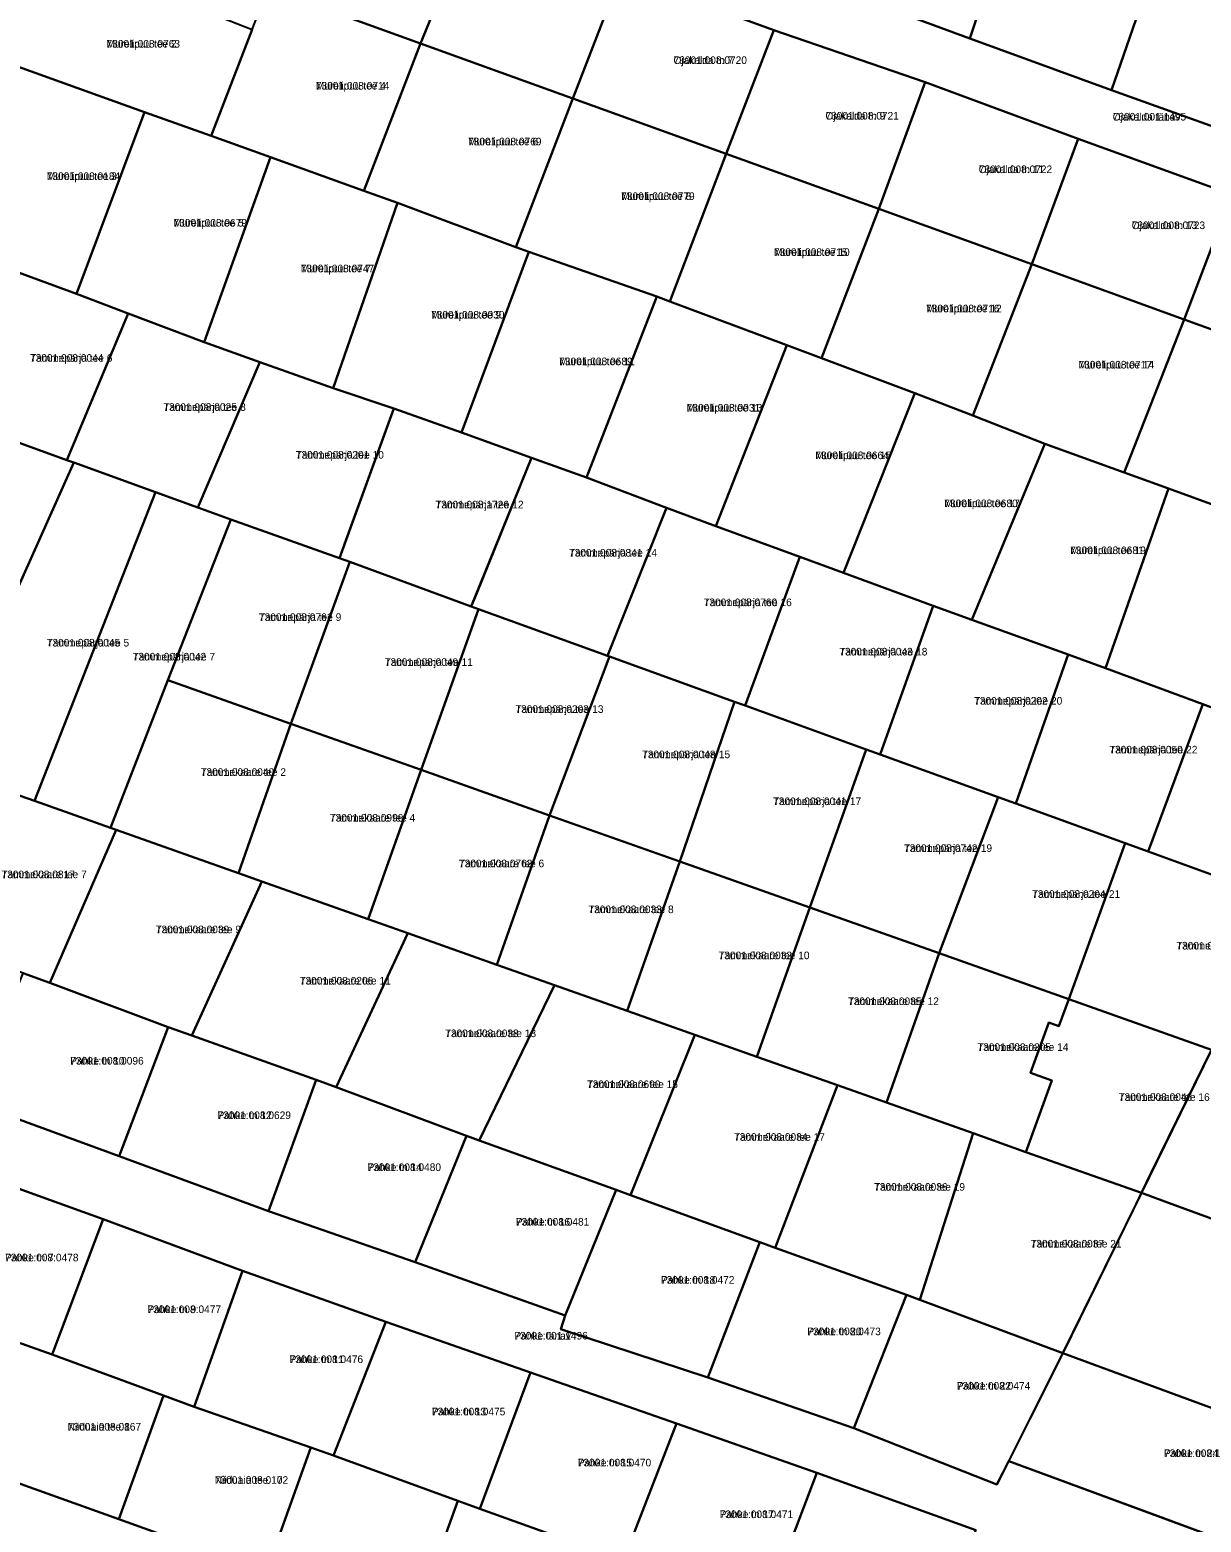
# Model space of a CAD drawing. Extents: x 524000 to 564260, y 6469338 to 6496391.
# Drawn here: x 535399.1 to 535630.3, y 6471359.9 to 6471654.6 of the extents above; entities that cross this region are included whole.
import ezdxf

# ---------------------------------------------------------------- set-up
doc = ezdxf.new("R2010")
doc.units = 0
for name, color, linetype in [('L_AADRESS', 7, 'Continuous'), ('PIIR', 7, 'Continuous'), ('TUNNUS', 7, 'Continuous')]:
    doc.layers.add(name, color=color, linetype=linetype)

msp = doc.modelspace()

# ---------------------------------------------------------------- linework, layer by layer
at = {"layer": 'PIIR'}
for points in [[(535636.37, 6471622.1), (535605.99, 6471633.1), (535575.78, 6471644.26), (535545.95, 6471654.54), (535515.72, 6471665.59), (535486.15, 6471676.39), (535455.47, 6471687.48), (535447.79, 6471690.25), (535461.42, 6471697.61), (535501.62, 6471683.31), (535528.82, 6471673.51), (535557.22, 6471663.01), (535584.62, 6471652.91), (535612.62, 6471642.71), (535639.99, 6471632.87)], [(535387.55, 6471442.79), (535416.68, 6471432.16), (535446.16, 6471421.31), (535475.12, 6471411.21), (535504.76, 6471400.7), (535503.9, 6471397.99), (535532.92, 6471388.42), (535561.75, 6471378.45), (535589.97, 6471367.28), (535592.34, 6471371.9), (535645.63, 6471352.25)], [(535585.83, 6471358.28), (535554.41, 6471369.63), (535526.7, 6471379.34), (535497.92, 6471389.42), (535469.32, 6471399.44), (535441.03, 6471409.53), (535413.56, 6471419.69), (535385.56, 6471429.81)], [(535321.36, 6471351.63), (535304.08, 6471400.35), (535329.03, 6471391.87), (535358.51, 6471381.29), (535387.56, 6471370.87), (535416.63, 6471360.43), (535445.69, 6471350)]]:
    msp.add_lwpolyline(points, dxfattribs=at)
for points in [[(535565.62, 6471688.81), (535584.52, 6471682.31), (535593.32, 6471679.01), (535584.62, 6471652.91), (535557.22, 6471663.01)], [(535455.47, 6471687.48), (535486.15, 6471676.39), (535476.16, 6471651.91), (535446.08, 6471662.8)], [(535593.32, 6471679.01), (535614.72, 6471671.41), (535621.6, 6471668.85), (535612.62, 6471642.71), (535584.62, 6471652.91)], [(535486.15, 6471676.39), (535515.72, 6471665.59), (535506.24, 6471641.03), (535476.16, 6471651.91)], [(535380.64, 6471653.45), (535385.87, 6471656.69), (535407.58, 6471668.53), (535442.96, 6471654.66), (535434.86, 6471633.66), (535421.72, 6471638.36), (535395.91, 6471647.63)], [(535621.6, 6471668.85), (535643.31, 6471660.9), (535649.15, 6471658.62), (535639.99, 6471632.87), (535612.62, 6471642.71)], [(535515.72, 6471665.59), (535545.95, 6471654.54), (535536.51, 6471630.12), (535506.24, 6471641.03)], [(535434.86, 6471633.66), (535442.96, 6471654.66), (535446.08, 6471662.8), (535476.16, 6471651.91), (535464.96, 6471622.82), (535446.58, 6471629.46)], [(535545.95, 6471654.54), (535575.78, 6471644.26), (535566.68, 6471619.22), (535536.51, 6471630.12)], [(535464.96, 6471622.82), (535476.16, 6471651.91), (535506.24, 6471641.03), (535495, 6471611.68), (535471.61, 6471620.42)], [(535383.06, 6471611.74), (535395.91, 6471647.63), (535421.72, 6471638.36), (535408.26, 6471602.44), (535392.25, 6471608.35)], [(535575.78, 6471644.26), (535605.99, 6471633.1), (535596.84, 6471608.35), (535566.68, 6471619.22)], [(535495, 6471611.68), (535506.24, 6471641.03), (535536.51, 6471630.12), (535525.38, 6471600.97), (535522.85, 6471601.91), (535497.53, 6471610.74)], [(535408.26, 6471602.44), (535421.72, 6471638.36), (535434.86, 6471633.66), (535446.58, 6471629.46), (535433.46, 6471592.9), (535418.44, 6471598.59)], [(535605.99, 6471633.1), (535636.37, 6471622.1), (535626.91, 6471597.4), (535596.84, 6471608.35)], [(535536.51, 6471630.12), (535566.68, 6471619.22), (535555.32, 6471589.78), (535548.47, 6471592.34), (535525.38, 6471600.97)], [(535433.46, 6471592.9), (535446.58, 6471629.46), (535464.96, 6471622.82), (535471.61, 6471620.42), (535458.96, 6471583.86), (535444.48, 6471588.99)], [(535636.37, 6471622.1), (535666.31, 6471611.28), (535656.91, 6471586.54), (535626.91, 6471597.4)], [(535458.96, 6471583.86), (535471.61, 6471620.42), (535495, 6471611.68), (535497.53, 6471610.74), (535484.26, 6471575.09), (535470.88, 6471579.82)], [(535555.32, 6471589.78), (535566.68, 6471619.22), (535596.84, 6471608.35), (535585.23, 6471578.4), (535573.79, 6471582.87)], [(535484.26, 6471575.09), (535497.53, 6471610.74), (535522.85, 6471601.91), (535508.97, 6471566.19), (535498.08, 6471570.05)], [(535392.25, 6471608.35), (535408.26, 6471602.44), (535418.44, 6471598.59), (535406.34, 6471569.64), (535379.72, 6471579.28)], [(535585.23, 6471578.4), (535596.84, 6471608.35), (535626.91, 6471597.4), (535615.11, 6471567.16), (535599.44, 6471572.85)], [(535508.97, 6471566.19), (535522.85, 6471601.91), (535525.38, 6471600.97), (535548.47, 6471592.34), (535534.46, 6471556.56), (535524.77, 6471560.22)], [(535407.73, 6471569.15), (535406.34, 6471569.64), (535418.44, 6471598.59), (535433.46, 6471592.9), (535444.48, 6471588.99), (535432.23, 6471560.27), (535423.84, 6471563.31)], [(535615.11, 6471567.16), (535626.91, 6471597.4), (535656.91, 6471586.54), (535646.98, 6471562.26), (535644.74, 6471556.41), (535623.82, 6471564)], [(535534.46, 6471556.56), (535548.47, 6471592.34), (535555.32, 6471589.78), (535573.79, 6471582.87), (535559.71, 6471547.36), (535551.07, 6471550.51)], [(535432.23, 6471560.27), (535444.48, 6471588.99), (535458.96, 6471583.86), (535470.88, 6471579.82), (535460.19, 6471550.27), (535438.72, 6471557.92)], [(535368.36, 6471583.4), (535379.72, 6471579.28), (535406.34, 6471569.64), (535407.73, 6471569.15), (535395.99, 6471542.77), (535358.36, 6471557.3)], [(535559.71, 6471547.36), (535573.79, 6471582.87), (535585.23, 6471578.4), (535599.44, 6471572.85), (535585.04, 6471538.05), (535577.41, 6471540.85)], [(535498.08, 6471570.05), (535487.2, 6471543.2), (535486.18, 6471540.68), (535462.24, 6471549.51), (535460.19, 6471550.27), (535461.17, 6471553), (535470.88, 6471579.82), (535484.26, 6471575.09)], [(535599.44, 6471572.85), (535615.11, 6471567.16), (535623.82, 6471564), (535611.41, 6471528.56), (535604.03, 6471531.22), (535585.04, 6471538.05)], [(535380.94, 6471508.97), (535387.06, 6471522.71), (535395.99, 6471542.77), (535407.73, 6471569.15), (535423.84, 6471563.31), (535399.98, 6471502.3), (535384.47, 6471507.73)], [(535486.18, 6471540.68), (535498.08, 6471570.05), (535508.97, 6471566.19), (535524.77, 6471560.22), (535513.09, 6471530.98), (535487.63, 6471540.2)], [(535399.98, 6471502.3), (535423.84, 6471563.31), (535432.23, 6471560.27), (535438.72, 6471557.92), (535426.29, 6471526.15), (535414.97, 6471496.99)], [(535623.82, 6471564), (535644.74, 6471556.41), (535649.36, 6471554.73), (535636.76, 6471519.12), (535630.62, 6471521.41), (535611.41, 6471528.56)], [(535513.09, 6471530.98), (535524.77, 6471560.22), (535534.46, 6471556.56), (535551.07, 6471550.51), (535540.3, 6471521.13), (535538.17, 6471521.9), (535513.5, 6471530.83)], [(535438.72, 6471557.92), (535460.19, 6471550.27), (535462.24, 6471549.51), (535450.6, 6471517.54), (535426.29, 6471526.15)], [(535551.07, 6471550.51), (535559.71, 6471547.36), (535577.41, 6471540.85), (535566.93, 6471511.48), (535564.18, 6471512.47), (535540.3, 6471521.13)], [(535462.24, 6471549.51), (535486.18, 6471540.68), (535487.63, 6471540.2), (535476.33, 6471508.43), (535450.6, 6471517.54)], [(535487.63, 6471540.2), (535513.09, 6471530.98), (535513.5, 6471530.83), (535501.65, 6471499.46), (535476.33, 6471508.43)], [(535577.41, 6471540.85), (535585.04, 6471538.05), (535604.03, 6471531.22), (535593.71, 6471501.78), (535590.2, 6471503.05), (535566.93, 6471511.48)], [(535513.5, 6471530.83), (535538.17, 6471521.9), (535527.38, 6471490.35), (535501.65, 6471499.46)], [(535604.03, 6471531.22), (535611.41, 6471528.56), (535630.62, 6471521.41), (535619.8, 6471492.33), (535615.27, 6471493.97), (535593.71, 6471501.78)], [(535414.97, 6471496.99), (535426.29, 6471526.15), (535450.6, 6471517.54), (535440.25, 6471488.02), (535416.12, 6471496.57)], [(535538.17, 6471521.9), (535540.3, 6471521.13), (535564.18, 6471512.47), (535553.04, 6471481.26), (535527.38, 6471490.35)], [(535630.62, 6471521.41), (535636.76, 6471519.12), (535660.07, 6471510.38), (535646.63, 6471482.61), (535619.8, 6471492.33)], [(535440.25, 6471488.02), (535450.6, 6471517.54), (535476.33, 6471508.43), (535465.87, 6471478.95), (535444.86, 6471486.39)], [(535564.18, 6471512.47), (535566.93, 6471511.48), (535590.2, 6471503.05), (535588.69, 6471499.05), (535578.54, 6471472.23), (535553.04, 6471481.26)], [(535382.37, 6471503.17), (535384.47, 6471507.73), (535399.98, 6471502.3), (535414.97, 6471496.99), (535416.12, 6471496.57), (535402.97, 6471466.37), (535397.72, 6471468.32), (535370.86, 6471478.25)], [(535465.87, 6471478.95), (535476.33, 6471508.43), (535501.65, 6471499.46), (535491.25, 6471469.96), (535473.66, 6471476.19)], [(535588.69, 6471499.05), (535590.2, 6471503.05), (535593.71, 6471501.78), (535615.27, 6471493.97), (535604.15, 6471463.16), (535578.54, 6471472.23)], [(535491.25, 6471469.96), (535501.65, 6471499.46), (535527.38, 6471490.35), (535517, 6471460.84), (535502.6, 6471465.94)], [(535416.12, 6471496.57), (535440.25, 6471488.02), (535444.86, 6471486.39), (535431.05, 6471455.95), (535426.34, 6471457.64), (535402.97, 6471466.37)], [(535615.27, 6471493.97), (535619.8, 6471492.33), (535646.63, 6471482.61), (535632.36, 6471453.17), (535604.15, 6471463.16)], [(535517, 6471460.84), (535527.38, 6471490.35), (535553.04, 6471481.26), (535542.6, 6471451.77), (535530.3, 6471456.13)], [(535444.86, 6471486.39), (535465.87, 6471478.95), (535473.66, 6471476.19), (535459.51, 6471445.76), (535455.57, 6471447.23), (535431.05, 6471455.95)], [(535542.6, 6471451.77), (535553.04, 6471481.26), (535578.54, 6471472.23), (535568.14, 6471442.73), (535558.48, 6471446.15)], [(535473.66, 6471476.19), (535491.25, 6471469.96), (535502.6, 6471465.94), (535487.79, 6471435.26), (535485.25, 6471436.18), (535459.51, 6471445.76)], [(535568.14, 6471442.73), (535578.54, 6471472.23), (535604.15, 6471463.16), (535602.22, 6471457.85), (535600.22, 6471458.58), (535596.6, 6471448.62), (535600.83, 6471447.08), (535595.69, 6471432.95), (535585.27, 6471436.66)], [(535397.72, 6471468.32), (535402.97, 6471466.37), (535426.34, 6471457.64), (535416.68, 6471432.16), (535387.55, 6471442.79)], [(535502.6, 6471465.94), (535517, 6471460.84), (535530.3, 6471456.13), (535517.66, 6471424.45), (535514.8, 6471425.49), (535487.79, 6471435.26)], [(535600.83, 6471447.08), (535596.6, 6471448.62), (535600.22, 6471458.58), (535602.22, 6471457.85), (535604.15, 6471463.16), (535632.36, 6471453.17), (535618.51, 6471424.89), (535595.69, 6471432.95)], [(535426.34, 6471457.64), (535431.05, 6471455.95), (535455.57, 6471447.23), (535446.16, 6471421.31), (535416.68, 6471432.16)], [(535530.3, 6471456.13), (535542.6, 6471451.77), (535558.48, 6471446.15), (535546.17, 6471414.06), (535543.15, 6471415.14), (535517.66, 6471424.45)], [(535632.36, 6471453.17), (535661.37, 6471442.52), (535679.4, 6471435.91), (535674.06, 6471424.59), (535667.34, 6471406.98), (535654.88, 6471411.55), (535623.09, 6471423.21), (535618.51, 6471424.88), (535620.45, 6471428.85)], [(535455.57, 6471447.23), (535459.51, 6471445.76), (535485.25, 6471436.18), (535475.12, 6471411.21), (535446.16, 6471421.31)], [(535558.48, 6471446.15), (535568.14, 6471442.73), (535585.27, 6471436.66), (535574.73, 6471403.8), (535572.09, 6471404.79), (535546.17, 6471414.06)], [(535485.25, 6471436.18), (535487.79, 6471435.26), (535514.8, 6471425.49), (535504.76, 6471400.7), (535475.12, 6471411.21)], [(535585.27, 6471436.66), (535595.69, 6471432.95), (535618.51, 6471424.89), (535602.98, 6471393.22), (535574.73, 6471403.8)], [(535385.56, 6471429.81), (535413.56, 6471419.69), (535403.45, 6471392.96), (535396.41, 6471395.49), (535374.56, 6471403.35)], [(535504.76, 6471400.7), (535514.8, 6471425.49), (535517.66, 6471424.45), (535543.15, 6471415.14), (535532.92, 6471388.42), (535503.9, 6471397.99)], [(535618.51, 6471424.88), (535623.09, 6471423.21), (535654.88, 6471411.55), (535667.34, 6471406.98), (535661.59, 6471392.43), (535653.82, 6471374.57), (535628.68, 6471383.78), (535602.98, 6471393.21), (535617.44, 6471422.7)], [(535413.56, 6471419.69), (535441.03, 6471409.53), (535431.48, 6471382.63), (535425.41, 6471384.87), (535403.45, 6471392.96)], [(535543.15, 6471415.14), (535546.17, 6471414.06), (535572.09, 6471404.79), (535561.75, 6471378.45), (535532.92, 6471388.42)], [(535441.03, 6471409.53), (535469.32, 6471399.44), (535458.97, 6471373.04), (535454.52, 6471374.59), (535431.48, 6471382.63)], [(535572.09, 6471404.79), (535574.73, 6471403.8), (535602.98, 6471393.22), (535589.97, 6471367.28), (535561.75, 6471378.45)], [(535469.32, 6471399.44), (535497.92, 6471389.42), (535487.91, 6471362.47), (535483.55, 6471364.06), (535458.97, 6471373.04)], [(535396.41, 6471395.49), (535403.45, 6471392.96), (535425.41, 6471384.87), (535416.63, 6471360.43), (535387.56, 6471370.87)], [(535602.98, 6471393.21), (535628.68, 6471383.78), (535653.82, 6471374.57), (535645.63, 6471352.25), (535623.05, 6471360.57), (535592.34, 6471371.9)], [(535497.92, 6471389.42), (535526.7, 6471379.34), (535516.22, 6471352.33), (535512.6, 6471353.63), (535487.91, 6471362.47)], [(535425.41, 6471384.87), (535431.48, 6471382.63), (535454.52, 6471374.59), (535445.69, 6471350), (535416.63, 6471360.43)], [(535526.7, 6471379.34), (535554.41, 6471369.63), (535543.97, 6471342), (535541.56, 6471342.9), (535516.22, 6471352.33)], [(535454.52, 6471374.59), (535458.97, 6471373.04), (535483.55, 6471364.06), (535474.75, 6471339.57), (535445.69, 6471350)], [(535554.41, 6471369.63), (535585.83, 6471358.28), (535572.02, 6471331.99), (535543.97, 6471342)], [(535483.55, 6471364.06), (535487.91, 6471362.47), (535512.6, 6471353.63), (535503.81, 6471329.14), (535474.75, 6471339.57)]]:
    msp.add_lwpolyline(points, close=True, dxfattribs=at)

# ---------------------------------------------------------------- texts
at = {"layer": 'L_AADRESS'}
for s, p in [('Murelipuu tee 2', (535414.2, 6471651.1)), ('Ojakalda tn 7', (535526.12, 6471647.86)), ('Murelipuu tee 4', (535455.52, 6471642.81)), ('Ojakalda tn 9', (535556.11, 6471636.88)), ('Ojakalda tänav', (535612.82, 6471636.69)), ('Murelipuu tee 6', (535485.56, 6471631.79)), ('Ojakalda tn 11', (535586.37, 6471626.31)), ('Murelipuu tee 3', (535402.39, 6471624.95)), ('Murelipuu tee 8', (535515.8, 6471621)), ('Murelipuu tee 5', (535427.42, 6471615.75)), ('Ojakalda tn 13', (535616.57, 6471615.25)), ('Murelipuu tee 10', (535545.96, 6471609.95)), ('Murelipuu tee 7', (535452.54, 6471606.72)), ('Murelipuu tee 12', (535575.97, 6471598.81)), ('Murelipuu tee 9', (535478.25, 6471597.58)), ('Tammepärja tee 6', (535399.08, 6471589.05)), ('Murelipuu tee 11', (535503.55, 6471588.37)), ('Murelipuu tee 14', (535606.07, 6471587.72)), ('Tammepärja tee 8', (535425.41, 6471579.35)), ('Murelipuu tee 13', (535528.72, 6471579.22)), ('Tammepärja tee 10', (535451.55, 6471569.92)), ('Murelipuu tee 15', (535554.12, 6471569.81)), ('Murelipuu tee 17', (535579.57, 6471560.33)), ('Tammepärja tee 12', (535479.13, 6471560.09)), ('Tammepärja tee 14', (535505.48, 6471550.58)), ('Murelipuu tee 19', (535604.43, 6471551.06)), ('Tammepärja tee 16', (535532.08, 6471540.78)), ('Tammepärja tee 9', (535444.27, 6471537.86)), ('Tammepärja tee 5', (535402.39, 6471532.81)), ('Tammepärja tee 18', (535558.85, 6471531.04)), ('Tammepärja tee 7', (535419.35, 6471530.05)), ('Tammepärja tee 11', (535469.12, 6471528.98)), ('Tammepärja tee 13', (535494.91, 6471519.7)), ('Tammepärja tee 20', (535585.48, 6471521.33)), ('Tammepärja tee 15', (535519.91, 6471510.75)), ('Tammepärja tee 22', (535612.16, 6471511.69)), ('Tammekaare tee 2', (535432.79, 6471507.26)), ('Tammepärja tee 17', (535545.78, 6471501.49)), ('Tammekaare tee 4', (535458.29, 6471498.23)), ('Tammepärja tee 19', (535571.62, 6471492.23)), ('Tammekaare tee 7', (535393.45, 6471487.05)), ('Tammekaare tee 6', (535483.76, 6471489.21)), ('Tammepärja tee 21', (535596.91, 6471483.17)), ('Tammekaare tee 8', (535509.32, 6471480.15)), ('Tammekaare tee 9', (535423.91, 6471476.18)), ('Tammepärja tee 23', (535625.39, 6471472.97)), ('Tammekaare tee 10', (535535.02, 6471471.05)), ('Tammekaare tee 11', (535452.35, 6471466.05)), ('Tammekaare tee 12', (535560.57, 6471462)), ('Tammekaare tee 13', (535481.05, 6471455.66)), ('Tammekaare tee 14', (535586.14, 6471452.94)), ('Pahke tn 10', (535407.03, 6471450.24)), ('Tammekaare tee 15', (535509.04, 6471445.61)), ('Tammekaare tee 16', (535614.02, 6471443.07)), ('Pahke tn 12', (535436.1, 6471439.48)), ('Tammekaare tee 17', (535538.07, 6471435.19)), ('Pahke tn 14', (535465.73, 6471429.22)), ('Tammekaare tee 19', (535565.72, 6471425.33)), ('Pahke tn 16', (535495, 6471418.44)), ('Tammekaare tee 21', (535596.62, 6471414.11)), ('Pahke tn 7', (535394.16, 6471411.38)), ('Pahke tn 18', (535523.65, 6471406.96)), ('Pahke tn 9', (535422.3, 6471401.16)), ('Pahke tänav', (535494.71, 6471395.94)), ('Pahke tn 20', (535552.54, 6471396.79)), ('Pahke tn 11', (535450.34, 6471391.29)), ('Pahke tn 22', (535582.05, 6471386.04)), ('Pahke tn 13', (535478.42, 6471380.96)), ('Niiduaia tee 8', (535406.52, 6471377.96)), ('Pahke tn 24', (535622.95, 6471372.73)), ('Pahke tn 15', (535507.22, 6471370.88)), ('Niiduaia tee 10', (535435.55, 6471367.44)), ('Pahke tn 17', (535535.24, 6471360.67))]:
    msp.add_text(s, height=1.5, dxfattribs=at).set_placement(p)
at = {"layer": 'TUNNUS'}
for s, p in [('73001:008:0763', (535414.2, 6471651.1)), ('73001:008:0720', (535526.12, 6471647.86)), ('73001:008:0714', (535455.52, 6471642.81)), ('73001:008:0721', (535556.11, 6471636.88)), ('73001:001:1495', (535612.82, 6471636.69)), ('73001:008:0769', (535485.56, 6471631.79)), ('73001:008:0722', (535586.37, 6471626.31)), ('73001:008:0184', (535402.39, 6471624.95)), ('73001:008:0779', (535515.8, 6471621)), ('73001:008:0679', (535427.42, 6471615.75)), ('73001:008:0723', (535616.57, 6471615.25)), ('73001:008:0715', (535545.96, 6471609.95)), ('73001:008:0747', (535452.54, 6471606.72)), ('73001:008:0716', (535575.97, 6471598.81)), ('73001:008:0030', (535478.25, 6471597.58)), ('73001:008:0044', (535399.08, 6471589.05)), ('73001:008:0689', (535503.55, 6471588.37)), ('73001:008:0717', (535606.07, 6471587.72)), ('73001:008:0025', (535425.41, 6471579.35)), ('73001:008:0031', (535528.72, 6471579.22)), ('73001:008:0201', (535451.55, 6471569.92)), ('73001:008:0664', (535554.12, 6471569.81)), ('73001:008:0680', (535579.57, 6471560.33)), ('73001:008:1726', (535479.13, 6471560.09)), ('73001:008:0841', (535505.48, 6471550.58)), ('73001:008:0681', (535604.43, 6471551.06)), ('73001:008:0760', (535532.08, 6471540.78)), ('73001:008:0761', (535444.27, 6471537.86)), ('73001:008:0045', (535402.39, 6471532.81)), ('73001:008:0043', (535558.85, 6471531.04)), ('73001:008:0042', (535419.35, 6471530.05)), ('73001:008:0049', (535469.12, 6471528.98)), ('73001:008:0203', (535494.91, 6471519.7)), ('73001:008:0202', (535585.48, 6471521.33)), ('73001:008:0048', (535519.91, 6471510.75)), ('73001:008:0050', (535612.16, 6471511.69)), ('73001:008:0040', (535432.79, 6471507.26)), ('73001:008:0041', (535545.78, 6471501.49)), ('73001:008:0996', (535458.29, 6471498.23)), ('73001:008:0742', (535571.62, 6471492.23)), ('73001:008:0817', (535393.45, 6471487.05)), ('73001:008:0762', (535483.76, 6471489.21)), ('73001:008:0204', (535596.91, 6471483.17)), ('73001:008:0033', (535509.32, 6471480.15)), ('73001:008:0039', (535423.91, 6471476.18)), ('73001:008:0047', (535625.39, 6471472.97)), ('73001:008:0032', (535535.02, 6471471.05)), ('73001:008:0206', (535452.35, 6471466.05)), ('73001:008:0035', (535560.57, 6471462)), ('73001:008:0038', (535481.05, 6471455.66)), ('73001:008:0205', (535586.14, 6471452.94)), ('73001:008:0096', (535407.03, 6471450.24)), ('73001:008:0690', (535509.04, 6471445.61)), ('73001:008:0046', (535614.02, 6471443.07)), ('73001:008:0629', (535436.1, 6471439.48)), ('73001:008:0034', (535538.07, 6471435.19)), ('73001:008:0480', (535465.73, 6471429.22)), ('73001:008:0036', (535565.72, 6471425.33)), ('73001:008:0481', (535495, 6471418.44)), ('73001:008:0037', (535596.62, 6471414.11)), ('73001:008:0478', (535394.16, 6471411.38)), ('73001:008:0472', (535523.65, 6471406.96)), ('73001:008:0477', (535422.3, 6471401.16)), ('73001:001:1496', (535494.71, 6471395.94)), ('73001:008:0473', (535552.54, 6471396.79)), ('73001:008:0476', (535450.34, 6471391.29)), ('73001:008:0474', (535582.05, 6471386.04)), ('73001:008:0475', (535478.42, 6471380.96)), ('73001:008:0167', (535406.52, 6471377.96)), ('73001:008:1740', (535622.95, 6471372.73)), ('73001:008:0470', (535507.22, 6471370.88)), ('73001:008:0172', (535435.55, 6471367.44)), ('73001:008:0471', (535535.24, 6471360.67))]:
    msp.add_text(s, height=1.5, dxfattribs=at).set_placement(p)

doc.saveas('drawing.dxf')
